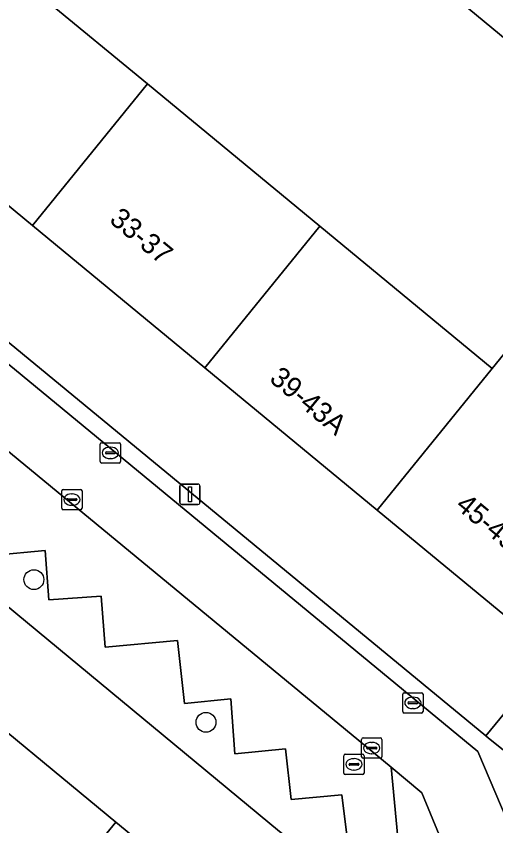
# Model space of a CAD drawing. Extents: x 162073 to 163043, y 381818 to 382561.
# Drawn here: x 162425.43 to 162449.04, y 382069.57 to 382109.4 of the extents above; entities that cross this region are included whole.
import ezdxf

# ---------------------------------------------------------------- set-up
doc = ezdxf.new("R2010")
doc.units = 0
for name, color, linetype in [('IMGEO_Boom', 7, 'Continuous'), ('IMGEO_Erf', 7, 'Continuous'), ('IMGEO_Kolk', 7, 'Continuous'), ('IMGEO_Lichtmast', 7, 'Continuous'), ('IMGEO_Pand', 7, 'Continuous'), ('IMGEO_Pand_nummerreeks', 7, 'Continuous'), ('IMGEO_Parkeervlak_open', 7, 'Continuous'), ('IMGEO_Rijbaan_lokaal_open', 7, 'Continuous'), ('IMGEO_Rioolput', 7, 'Continuous'), ('IMGEO_Voetpad_open', 7, 'Continuous')]:
    doc.layers.add(name, color=color, linetype=linetype)

msp = doc.modelspace()

# ---------------------------------------------------------------- linework, layer by layer
at = {"layer": 'IMGEO_Boom'}
for centre in [(162426.302, 382081.68), (162434.771, 382074.66)]:
    msp.add_circle(centre, 0.489, dxfattribs=at)
at = {"layer": 'IMGEO_Erf'}
for points in [[(162426.82, 382110.258), (162431.897, 382106.068), (162440.381, 382099.065), (162448.864, 382092.063), (162456.35, 382101.275), (162460.128, 382098.157), (162453.876, 382090.581), (162458.753, 382086.556), (162457.449, 382084.977), (162457.546, 382084.897), (162465.734, 382094.868), (162397.649, 382151.094), (162389.437, 382141.114), (162397.963, 382134.077), (162406.447, 382127.074), (162414.93, 382120.072), (162423.413, 382113.07), (162423.685, 382112.846), (162430.242, 382120.791), (162433.377, 382118.204)], [(162417.75, 382106.108), (162409.267, 382113.11), (162400.782, 382120.113), (162392.297, 382127.116), (162383.724, 382134.193), (162380.395, 382130.153), (162448.544, 382073.992), (162451.833, 382077.976), (162443.204, 382085.098), (162434.72, 382092.101), (162426.235, 382099.105)], [(162374.058, 382122.534), (162370.927, 382118.714), (162379.513, 382111.639), (162387.985, 382104.658), (162396.457, 382097.677), (162404.928, 382090.697), (162413.399, 382083.717), (162421.871, 382076.736), (162430.342, 382069.755), (162438.929, 382062.68), (162442.197, 382066.248), (162438.394, 382069.293)]]:
    msp.add_lwpolyline(points, close=True, dxfattribs=at)
at = {"layer": 'IMGEO_Kolk'}
for p, q in [((162429.64, 382088.415), (162430.492, 382088.415)), ((162429.565, 382087.489), (162429.565, 382088.341)), ((162430.053, 382088.195), (162430.078, 382088.195)), ((162430.566, 382088.341), (162430.566, 382087.489)), ((162429.824, 382087.909), (162429.824, 382087.921)), ((162430.262, 382087.872), (162429.864, 382087.872)), ((162429.867, 382087.958), (162430.265, 382087.958)), ((162430.076, 382087.635), (162430.051, 382087.635)), ((162430.308, 382087.921), (162430.308, 382087.909)), ((162430.492, 382087.415), (162429.64, 382087.415)), ((162427.671, 382085.19), (162427.671, 382086.042)), ((162427.746, 382086.116), (162428.598, 382086.116)), ((162428.672, 382086.042), (162428.672, 382085.19)), ((162427.93, 382085.61), (162427.93, 382085.622)), ((162428.368, 382085.573), (162427.97, 382085.573)), ((162427.973, 382085.659), (162428.371, 382085.659)), ((162428.159, 382085.896), (162428.184, 382085.896)), ((162428.414, 382085.622), (162428.414, 382085.61)), ((162428.182, 382085.336), (162428.157, 382085.336)), ((162428.598, 382085.116), (162427.746, 382085.116)), ((162444.453, 382075.191), (162444.453, 382076.043)), ((162444.528, 382076.117), (162445.38, 382076.117)), ((162445.454, 382076.043), (162445.454, 382075.191)), ((162444.712, 382075.611), (162444.712, 382075.623)), ((162444.755, 382075.66), (162445.153, 382075.66)), ((162444.941, 382075.897), (162444.966, 382075.897)), ((162445.196, 382075.623), (162445.196, 382075.611)), ((162445.15, 382075.574), (162444.752, 382075.574)), ((162444.964, 382075.337), (162444.939, 382075.337)), ((162445.38, 382075.117), (162444.528, 382075.117)), ((162442.43, 382072.968), (162442.43, 382073.82)), ((162442.505, 382073.894), (162443.357, 382073.894)), ((162442.918, 382073.674), (162442.943, 382073.674)), ((162443.431, 382073.82), (162443.431, 382072.968)), ((162442.689, 382073.388), (162442.689, 382073.4)), ((162443.127, 382073.351), (162442.729, 382073.351)), ((162442.732, 382073.437), (162443.13, 382073.437)), ((162443.173, 382073.4), (162443.173, 382073.388)), ((162443.357, 382072.894), (162442.505, 382072.894)), ((162442.941, 382073.114), (162442.916, 382073.114))]:
    msp.add_line(p, q, dxfattribs=at)
for points in [[(162429.64, 382088.415), (162430.492, 382088.415)], [(162429.565, 382087.489), (162429.565, 382088.341)], [(162430.566, 382088.341), (162430.566, 382087.489)], [(162430.492, 382087.415), (162429.64, 382087.415)], [(162427.671, 382085.19), (162427.671, 382086.042)], [(162427.746, 382086.116), (162428.598, 382086.116)], [(162428.672, 382086.042), (162428.672, 382085.19)], [(162428.598, 382085.116), (162427.746, 382085.116)], [(162444.453, 382075.191), (162444.453, 382076.043)], [(162444.528, 382076.117), (162445.38, 382076.117)], [(162445.454, 382076.043), (162445.454, 382075.191)], [(162445.38, 382075.117), (162444.528, 382075.117)], [(162442.43, 382072.968), (162442.43, 382073.82)], [(162442.505, 382073.894), (162443.357, 382073.894)], [(162443.431, 382073.82), (162443.431, 382072.968)], [(162443.357, 382072.894), (162442.505, 382072.894)]]:
    msp.add_lwpolyline(points, dxfattribs=at)
for centre, radius, start, end in [((162429.642, 382088.339), 0.0765, 91.552, 178.448), ((162429.642, 382088.339), 0.0765, 91.552, 178.448), ((162430.49, 382088.339), 0.0765, 1.552, 88.448), ((162430.49, 382088.339), 0.0765, 1.552, 88.448), ((162429.864, 382087.918), 0.0403, 85.8775, 175.7526), ((162429.861, 382087.908), 0.0366, 178.938, 274.7102), ((162430.265, 382087.915), 0.043, 264.8664, 352.4533), ((162430.269, 382087.92), 0.0386, 1.7309, 96.639), ((162429.642, 382087.491), 0.0765, 181.552, 268.448), ((162429.642, 382087.491), 0.0765, 181.552, 268.448), ((162430.49, 382087.491), 0.0765, 271.552, 358.448), ((162430.49, 382087.491), 0.0765, 271.552, 358.448), ((162427.748, 382086.04), 0.0765, 91.552, 178.448), ((162427.748, 382086.04), 0.0765, 91.552, 178.448), ((162428.596, 382086.04), 0.0765, 1.552, 88.448), ((162428.596, 382086.04), 0.0765, 1.552, 88.448), ((162427.97, 382085.619), 0.0403, 85.8775, 175.7526), ((162427.967, 382085.609), 0.0366, 178.938, 274.7102), ((162428.371, 382085.616), 0.043, 264.8664, 352.4533), ((162428.375, 382085.621), 0.0386, 1.7309, 96.639), ((162427.748, 382085.192), 0.0765, 181.552, 268.448), ((162427.748, 382085.192), 0.0765, 181.552, 268.448), ((162428.596, 382085.192), 0.0765, 271.552, 358.448), ((162428.596, 382085.192), 0.0765, 271.552, 358.448), ((162444.53, 382076.041), 0.0765, 91.552, 178.448), ((162444.53, 382076.041), 0.0765, 91.552, 178.448), ((162445.378, 382076.041), 0.0765, 1.552, 88.448), ((162445.378, 382076.041), 0.0765, 1.552, 88.448), ((162444.752, 382075.62), 0.0403, 85.8775, 175.7526), ((162445.157, 382075.622), 0.0386, 1.7309, 96.639), ((162444.749, 382075.61), 0.0366, 178.938, 274.7102), ((162445.153, 382075.617), 0.043, 264.8664, 352.4533), ((162444.53, 382075.193), 0.0765, 181.552, 268.448), ((162444.53, 382075.193), 0.0765, 181.552, 268.448), ((162445.378, 382075.193), 0.0765, 271.552, 358.448), ((162445.378, 382075.193), 0.0765, 271.552, 358.448), ((162442.507, 382073.818), 0.0765, 91.552, 178.448), ((162442.507, 382073.818), 0.0765, 91.552, 178.448), ((162443.355, 382073.818), 0.0765, 1.552, 88.448), ((162443.355, 382073.818), 0.0765, 1.552, 88.448), ((162442.729, 382073.397), 0.0403, 85.8775, 175.7526), ((162442.726, 382073.387), 0.0366, 178.938, 274.7102), ((162443.13, 382073.394), 0.043, 264.8664, 352.4533), ((162443.134, 382073.399), 0.0386, 1.7309, 96.639), ((162442.507, 382072.97), 0.0765, 181.552, 268.448), ((162442.507, 382072.97), 0.0765, 181.552, 268.448), ((162443.355, 382072.97), 0.0765, 271.552, 358.448), ((162443.355, 382072.97), 0.0765, 271.552, 358.448)]:
    msp.add_arc(centre, radius, start, end, dxfattribs=at)
for centre, major_axis, ratio, start_param, end_param in [((162430.052, 382087.915), (-0.387, 0.002), 0.722429, 4.712389, 7.853982), ((162430.077, 382087.915), (-0.39, 0.002), 0.717154, 1.570796, 4.712389), ((162428.158, 382085.616), (-0.387, 0.002), 0.722429, 4.712389, 7.853982), ((162428.183, 382085.616), (-0.39, 0.002), 0.717154, 1.570796, 4.712389), ((162444.94, 382075.617), (-0.387, 0.002), 0.722429, 4.712389, 7.853982), ((162444.965, 382075.617), (-0.39, 0.002), 0.717154, 1.570796, 4.712389), ((162442.917, 382073.394), (-0.387, 0.002), 0.722429, 4.712389, 7.853982), ((162442.942, 382073.394), (-0.39, 0.002), 0.717154, 1.570796, 4.712389)]:
    msp.add_ellipse(centre, major_axis=major_axis, ratio=ratio, start_param=start_param, end_param=end_param, dxfattribs=at)
at = {"layer": 'IMGEO_Lichtmast'}
for p, q in [((162433.584, 382086.376), (162434.374, 382086.376)), ((162434.374, 382086.376), (162433.584, 382086.376)), ((162433.484, 382085.476), (162433.484, 382086.276)), ((162433.484, 382086.276), (162433.484, 382085.476)), ((162434.474, 382086.276), (162434.474, 382085.476)), ((162434.474, 382085.476), (162434.474, 382086.276)), ((162434.374, 382085.376), (162433.584, 382085.376)), ((162433.584, 382085.376), (162434.374, 382085.376))]:
    msp.add_line(p, q, dxfattribs=at)
msp.add_lwpolyline([(162433.904, 382086.251), (162434.054, 382086.251), (162434.054, 382085.501), (162433.904, 382085.501), (162433.904, 382086.251)], dxfattribs=at)
for centre, start, end in [((162433.584, 382086.276), 90, 180), ((162433.584, 382086.276), 90, 180), ((162434.374, 382086.276), 0, 90), ((162434.374, 382086.276), 360, 90), ((162433.584, 382085.476), 180, 270), ((162433.584, 382085.476), 180, 270), ((162434.374, 382085.476), 270, 0), ((162434.374, 382085.476), 270, 0)]:
    msp.add_arc(centre, 0.1, start, end, dxfattribs=at)
at = {"layer": 'IMGEO_Pand'}
for points in [[(162426.82, 382110.258), (162433.377, 382118.204), (162430.242, 382120.791), (162423.685, 382112.846), (162423.413, 382113.07), (162417.75, 382106.108), (162426.235, 382099.105), (162431.897, 382106.068)], [(162431.897, 382106.068), (162426.235, 382099.105), (162434.72, 382092.101), (162440.381, 382099.065)], [(162448.864, 382092.063), (162443.204, 382085.098), (162451.833, 382077.976), (162455.016, 382081.832), (162457.546, 382084.897), (162457.449, 382084.977), (162458.753, 382086.556), (162453.876, 382090.581), (162460.128, 382098.157), (162456.35, 382101.275)], [(162440.381, 382099.065), (162434.72, 382092.101), (162443.204, 382085.098), (162448.864, 382092.063)], [(162424.572, 382062.752), (162430.342, 382069.755), (162421.871, 382076.736), (162416.1, 382069.733)], [(162424.572, 382062.752), (162433.159, 382055.677), (162435.75, 382058.822), (162438.929, 382062.68), (162430.342, 382069.755)]]:
    msp.add_lwpolyline(points, close=True, dxfattribs=at)
at = {"layer": 'IMGEO_Parkeervlak_open'}
for points in [[(162444.221, 382068.98), (162443.882, 382072.46), (162383.272, 382122.429)], [(162424.388, 382082.888), (162426.86, 382083.109), (162427.045, 382080.693), (162429.611, 382080.866), (162429.813, 382078.35), (162433.368, 382078.685), (162433.706, 382075.579), (162435.989, 382075.816), (162436.19, 382073.11), (162438.688, 382073.348), (162438.969, 382070.857), (162441.451, 382071.1), (162441.755, 382068.708)]]:
    msp.add_lwpolyline(points, dxfattribs=at)
at = {"layer": 'IMGEO_Rijbaan_lokaal_open'}
for points in [[(162450.473, 382067.754), (162448.153, 382073.217), (162382.822, 382127.114), (162375.036, 382129.973), (162374.57, 382130.393), (162373.697, 382131.117), (162359.38, 382142.904), (162358.519, 382143.628)], [(162356.428, 382141.01), (162357.272, 382140.243), (162371.197, 382128.843), (162372.287, 382127.917), (162373.341, 382127.019), (162381.182, 382124.132), (162383.272, 382122.429), (162443.882, 382072.46), (162445.4, 382071.193), (162447.637, 382065.739)]]:
    msp.add_lwpolyline(points, dxfattribs=at)
at = {"layer": 'IMGEO_Rioolput'}
for p, q in [((162441.552, 382072.166), (162441.552, 382073.018)), ((162441.627, 382073.092), (162442.479, 382073.092)), ((162442.04, 382072.872), (162442.065, 382072.872)), ((162442.553, 382073.018), (162442.553, 382072.166)), ((162441.811, 382072.586), (162441.811, 382072.598)), ((162442.249, 382072.549), (162441.851, 382072.549)), ((162441.854, 382072.635), (162442.252, 382072.635)), ((162442.295, 382072.598), (162442.295, 382072.586)), ((162442.479, 382072.092), (162441.627, 382072.092)), ((162442.063, 382072.312), (162442.038, 382072.312))]:
    msp.add_line(p, q, dxfattribs=at)
for points in [[(162441.552, 382072.166), (162441.552, 382073.018)], [(162441.627, 382073.092), (162442.479, 382073.092)], [(162442.553, 382073.018), (162442.553, 382072.166)], [(162442.479, 382072.092), (162441.627, 382072.092)]]:
    msp.add_lwpolyline(points, dxfattribs=at)
for centre, radius, start, end in [((162441.629, 382073.016), 0.0765, 91.552, 178.448), ((162441.629, 382073.016), 0.0765, 91.552, 178.448), ((162442.477, 382073.016), 0.0765, 1.552, 88.448), ((162442.477, 382073.016), 0.0765, 1.552, 88.448), ((162441.851, 382072.595), 0.0403, 85.8775, 175.7526), ((162441.848, 382072.585), 0.0366, 178.938, 274.7102), ((162442.252, 382072.592), 0.043, 264.8664, 352.4533), ((162442.256, 382072.597), 0.0386, 1.7309, 96.639), ((162441.629, 382072.168), 0.0765, 181.552, 268.448), ((162441.629, 382072.168), 0.0765, 181.552, 268.448), ((162442.477, 382072.168), 0.0765, 271.552, 358.448), ((162442.477, 382072.168), 0.0765, 271.552, 358.448)]:
    msp.add_arc(centre, radius, start, end, dxfattribs=at)
for centre, major_axis, ratio, start_param, end_param in [((162442.039, 382072.592), (-0.387, 0.002), 0.722429, 4.712389, 7.853982), ((162442.064, 382072.592), (-0.39, 0.002), 0.717154, 1.570796, 4.712389)]:
    msp.add_ellipse(centre, major_axis=major_axis, ratio=ratio, start_param=start_param, end_param=end_param, dxfattribs=at)
at = {"layer": 'IMGEO_Voetpad_open'}
for points in [[(162394.961, 382150.627), (162392.595, 382147.754), (162390.577, 382145.343), (162387.984, 382142.193), (162385.618, 382139.32), (162379.006, 382131.297), (162380.395, 382130.153), (162383.724, 382134.193), (162386.907, 382138.049), (162389.437, 382141.114), (162397.649, 382151.094), (162465.734, 382094.868)], [(162453.791, 382069.764), (162453.132, 382070.292), (162452.152, 382071.11), (162448.681, 382073.879), (162448.544, 382073.992), (162380.395, 382130.153), (162379.006, 382131.297), (162363.474, 382144.097)], [(162356.934, 382136.569), (162372.628, 382123.707), (162374.058, 382122.534), (162438.394, 382069.293), (162442.197, 382066.248), (162443.042, 382065.571), (162446.525, 382062.616), (162454.536, 382056.174)], [(162374.57, 382130.393), (162375.036, 382129.973), (162382.822, 382127.114), (162448.153, 382073.217), (162450.473, 382067.754), (162451.851, 382066.605)], [(162438.688, 382073.348), (162436.19, 382073.11), (162435.989, 382075.816), (162433.706, 382075.579), (162433.368, 382078.685), (162429.813, 382078.35), (162429.611, 382080.866), (162427.045, 382080.693), (162426.86, 382083.109), (162424.388, 382082.888)], [(162451.833, 382077.976), (162448.544, 382073.992), (162448.681, 382073.879), (162452.152, 382071.11)], [(162449.709, 382064.013), (162447.637, 382065.739), (162445.4, 382071.193), (162443.882, 382072.46), (162444.221, 382068.98), (162441.755, 382068.708), (162441.451, 382071.1), (162438.969, 382070.857), (162438.688, 382073.348)]]:
    msp.add_lwpolyline(points, dxfattribs=at)

# ---------------------------------------------------------------- texts
at = {"layer": 'IMGEO_Pand_nummerreeks'}
for s, rotation, p in [('33-37', 320.4638, (162429.964, 382099.294)), ('39-43A', 320.4602, (162437.84, 382091.471)), ('45-49', 320.4659, (162447.002, 382085.231))]:
    msp.add_text(s, height=1, rotation=rotation, dxfattribs=at).set_placement(p)

doc.saveas('drawing.dxf')
